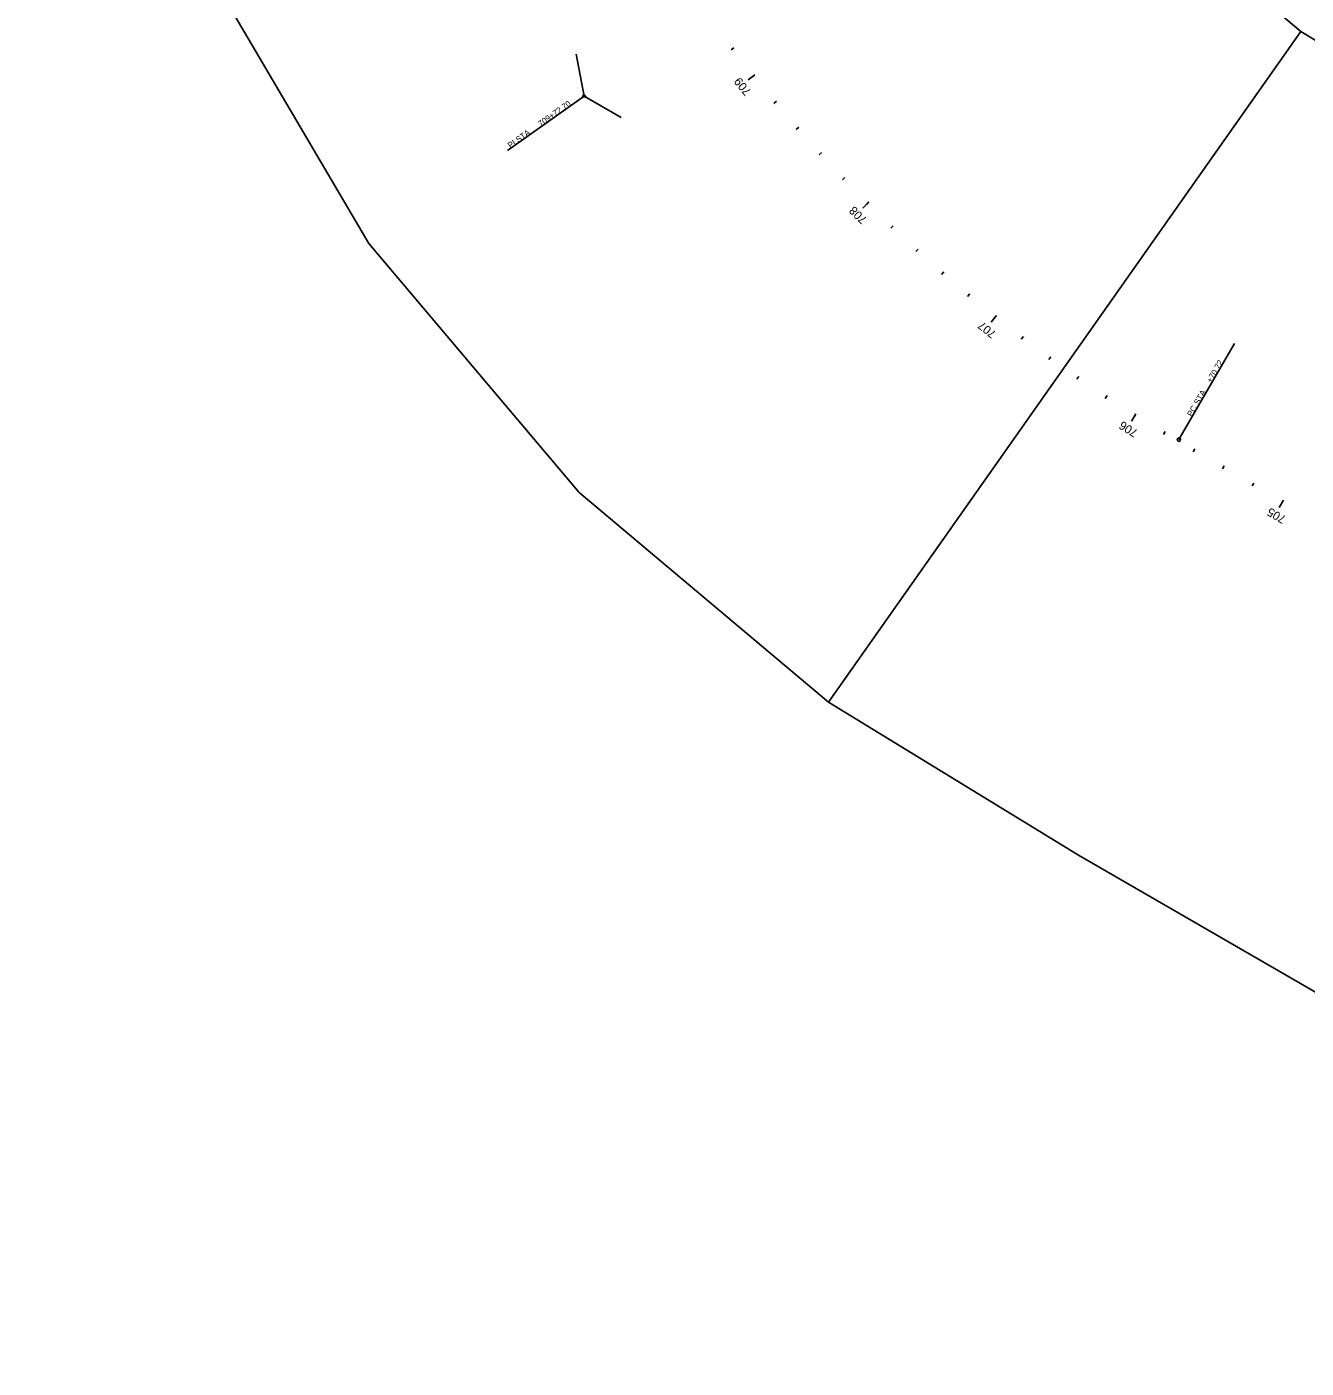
# Model space of a CAD drawing. Extents: x 2005381 to 2007040, y 402385 to 405116.
# Drawn here: x 2005665 to 2006414, y 402385 to 403170 of the extents above; entities that cross this region are included whole.
import ezdxf

# ---------------------------------------------------------------- set-up
doc = ezdxf.new("R2010")
doc.units = 0
for name, color, linetype in [('ClipDrawingBound_dp', 7, 'Continuous'), ('TextAlgnCardinalPnt', 7, 'Continuous'), ('TextAlgnStation100', 7, 'Continuous'), ('TextAlgnStation500', 7, 'Continuous'), ('TextAlgnTicks100', 7, 'Continuous'), ('TextAlgnTicks1000', 7, 'Continuous'), ('TextAlgnTicks500', 7, 'Continuous')]:
    doc.layers.add(name, color=color, linetype=linetype)

msp = doc.modelspace()

# ---------------------------------------------------------------- linework, layer by layer
at = {"layer": 'ClipDrawingBound_dp'}
for points in [[(2006134.42, 402774.87), (2006410.87, 403167.27), (2006327.42, 403237.4), (2006257.05, 403320.66), (2006201.81, 403414.63), (2006163.3, 403516.6), (2006136.44, 403643.32), (2005665.17, 403552.24), (2005701.47, 403385.79), (2005768.83, 403207.46), (2005865.43, 403043.12), (2005988.48, 402897.52)], [(2006800.2, 402385.11), (2007040.26, 402800.77), (2006910.37, 402875.79), (2006780.48, 402950.81), (2006650.59, 403025.83), (2006520.69, 403100.85), (2006410.87, 403167.27), (2006134.42, 402774.87), (2006280.63, 402685.19), (2006410.52, 402610.17), (2006540.41, 402535.15), (2006670.31, 402460.13)]]:
    msp.add_lwpolyline(points, close=True, dxfattribs=at)
at = {"layer": 'TextAlgnCardinalPnt'}
for p, q in [((2005991.32, 403129.44), (2005986.58, 403153.98)), ((2005991.32, 403129.44), (2005946.53, 403097.53)), ((2005991.32, 403129.44), (2006012.97, 403116.93)), ((2006339.42, 402928.39), (2006371.93, 402984.68))]:
    msp.add_line(p, q, dxfattribs=at)
msp.add_lwpolyline([(2005990.38, 403128.77), (2005992.37, 403128.96), (2005991.21, 403130.58)], close=True, dxfattribs=at)
msp.add_circle((2006339.42, 402928.39), 1, dxfattribs=at)
at = {"layer": 'TextAlgnTicks100'}
for p, q in [((2006079, 403157.71), (2006077.41, 403156.5)), ((2006091.29, 403141.93), (2006087.38, 403138.82)), ((2006103.94, 403126.44), (2006102.41, 403125.16)), ((2006116.94, 403111.24), (2006115.43, 403109.92)), ((2006130.27, 403096.34), (2006128.8, 403094.99)), ((2006143.95, 403081.74), (2006142.5, 403080.36)), ((2006157.95, 403067.46), (2006154.42, 403063.92)), ((2006172.27, 403053.5), (2006170.89, 403052.05)), ((2006186.9, 403039.87), (2006185.56, 403038.39)), ((2006201.84, 403026.57), (2006200.53, 403025.06)), ((2006217.08, 403013.62), (2006215.8, 403012.08)), ((2006232.61, 403001.01), (2006229.5, 402997.1)), ((2006248.42, 402988.77), (2006247.21, 402987.17)), ((2006264.5, 402976.88), (2006263.33, 402975.26)), ((2006280.85, 402965.36), (2006279.72, 402963.71)), ((2006297.46, 402954.22), (2006296.36, 402952.54)), ((2006314.31, 402943.45), (2006311.67, 402939.21)), ((2006331.41, 402933.07), (2006330.39, 402931.35)), ((2006348.7, 402923.03), (2006347.7, 402921.3)), ((2006366.02, 402913.03), (2006365.02, 402911.29)), ((2006383.34, 402903.02), (2006382.34, 402901.29)), ((2006400.66, 402893.02), (2006398.16, 402888.69))]:
    msp.add_line(p, q, dxfattribs=at)
at = {"layer": 'TextAlgnTicks1000'}
for p, q in [((2006157.95, 403067.46), (2006156.54, 403066.04)), ((2006314.31, 402943.45), (2006313.26, 402941.75))]:
    msp.add_line(p, q, dxfattribs=at)
at = {"layer": 'TextAlgnTicks500'}
for p, q in [((2006091.29, 403141.93), (2006089.73, 403140.69)), ((2006157.95, 403067.46), (2006156.54, 403066.04)), ((2006232.61, 403001.01), (2006231.37, 402999.45)), ((2006314.31, 402943.45), (2006313.26, 402941.75)), ((2006400.66, 402893.02), (2006398.16, 402888.69))]:
    msp.add_line(p, q, dxfattribs=at)

# ---------------------------------------------------------------- texts
at = {"layer": 'TextAlgnCardinalPnt'}
for s, rotation, p in [('709+72.70', 35.465, (2005965.93, 403111.35)), ('PI STA. ', 35.465, (2005948.18, 403098.71)), ('+70.72', 59.99111, (2006358.4, 402961.26)), (' STA. ', 59.99111, (2006350.34, 402947.3)), ('PC', 59.99111, (2006347, 402941.52))]:
    msp.add_text(s, height=3.48, rotation=rotation, dxfattribs=at).set_placement(p)
at = {"layer": 'TextAlgnStation100'}
for s, rotation, p in [('709', 128.57673, (2006089.49, 403132.17)), ('708', 135.08022, (2006157.29, 403057.53)), ('707', 141.58372, (2006233, 402991.13)), ('706', 148.08721, (2006315.87, 402933.65)), ('705', 149.99111, (2006402.57, 402883.26))]:
    msp.add_text(s, height=4.98, rotation=rotation, dxfattribs=at).set_placement(p)
at = {"layer": 'TextAlgnStation500'}
msp.add_text('705', height=4.98, rotation=149.99111, dxfattribs=at).set_placement((2006402.57, 402883.26))

doc.saveas('drawing.dxf')
